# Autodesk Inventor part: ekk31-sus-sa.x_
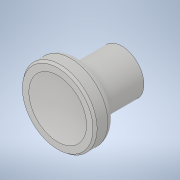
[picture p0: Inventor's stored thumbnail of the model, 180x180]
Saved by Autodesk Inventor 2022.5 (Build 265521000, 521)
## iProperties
Created: 2021-08
Part Number: ekk31-sus-sa.x_
Material: 一般
Document SubType Name: Modeling
Designer: ImaoCorp
Density: 1 g/cm^3
Appearance: 既定
Sending System: SOLIDWORKS 2019-2019304
MC: AMD64
MC_MODEL: Intel64 Family 6 Model 60 Stepping 3, GenuineIntel
OS: Windows_NT
FRU: Parasolid Version 31.0, build 290,  9- 1-2019
FORMAT: text
GUISE: transmit
KEY: ekk31-sus-sa
FILE: ekk31-sus-sa.x_t
DATE: Wed Aug 11 15:03:46 2021
Author: ImaoCorp
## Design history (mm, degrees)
feature "Base1"
node "ソリッド1"
